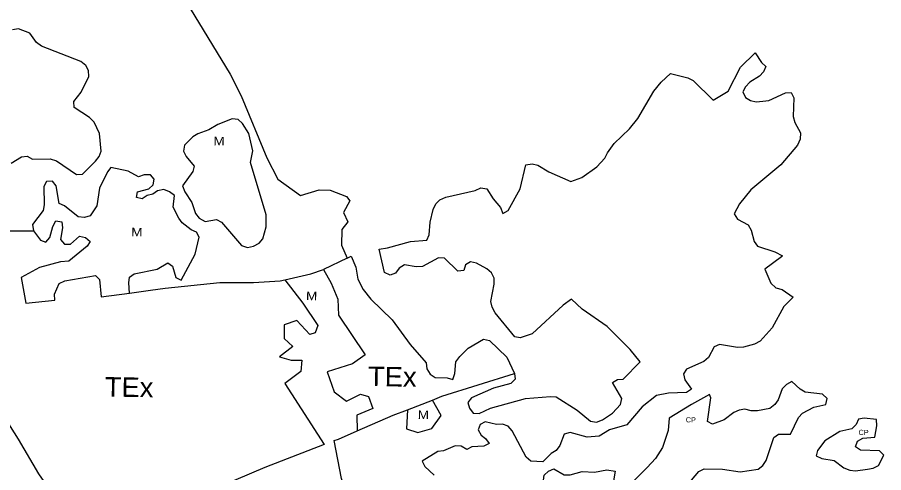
# Model space of a CAD drawing. Extents: x 713589 to 726391, y 7177764 to 7191819.
# Drawn here: x 719111 to 720179, y 7178472 to 7179033 of the extents above; entities that cross this region are included whole.
import ezdxf
from ezdxf.enums import TextEntityAlignment as Align

# ---------------------------------------------------------------- set-up
doc = ezdxf.new("R2010")
doc.units = 0
doc.header["$LTSCALE"] = 2.6
doc.layers.add('63', color=7, linetype='Continuous', lineweight=25)

msp = doc.modelspace()

# ---------------------------------------------------------------- linework, layer by layer
at = {"layer": '63'}
for p, q in [((719516.99, 7178736.28), (719487.86, 7178722.39)), ((719591.53, 7178549.49), (719622.15, 7178561.43))]:
    msp.add_line(p, q, dxfattribs=at)
for points in [[(718838.82, 7179163.06), (718828.12, 7179158.53), (718794.44, 7179144.27), (718739.17, 7179106.93), (718770.73, 7179057.83), (718801.73, 7179009.6), (718825.05, 7178971.22), (718875.74, 7178887.82), (718880.38, 7178880.19), (718880.89, 7178879.35), (718890.45, 7178864.16), (718971.65, 7178735.2), (719013.14, 7178669.3), (719106.43, 7178521.14), (719111.47, 7178513.14), (719136.8, 7178470.37), (719165.62, 7178428.86), (719189.56, 7178386.56), (719224.52, 7178313.68)], [(719323.63, 7179043.62), (719372.98, 7178962.99), (719386.46, 7178936), (719418.04, 7178859.65), (719431.53, 7178833.65), (719459.49, 7178813.24), (719482.53, 7178820.48), (719496.02, 7178819.82), (719516.42, 7178811.92), (719520.37, 7178806.98), (719512.47, 7178792.5), (719518.06, 7178780.99), (719510.49, 7178771.44), (719510.16, 7178752.03), (719516.99, 7178736.28)], [(719102.73, 7178852.99), (719115.57, 7178860.89), (719122.81, 7178861.87), (719129.06, 7178857.92), (719151.1, 7178858.58), (719158.67, 7178855.94), (719183.35, 7178839.16), (719190.92, 7178839.49), (719206.72, 7178855.61), (719211.33, 7178861.53), (719213.96, 7178868.11), (719211.66, 7178889.83), (719205.41, 7178903.65), (719199.49, 7178909.25), (719180.4, 7178921.75), (719180.08, 7178928.99), (719189.29, 7178940.51), (719198.51, 7178959.92), (719198.18, 7178967.16), (719194.89, 7178973.42), (719188.97, 7178978.35), (719140.27, 7178997.45), (719134.35, 7179001.73), (719125.79, 7179013.25), (719111.97, 7179018.51), (719104.73, 7179017.53)], [(719723.31, 7178594.23), (719724.3, 7178586.99), (719719.03, 7178581.73), (719697.64, 7178576.14), (719670.33, 7178563.97), (719666.05, 7178558.38), (719668.02, 7178551.46), (719672.3, 7178545.21), (719679.87, 7178544.88), (719693.69, 7178551.46), (719737.13, 7178563.3), (719767.73, 7178565.93), (719774.97, 7178565.27), (719800.64, 7178549.14), (719817.09, 7178535.31), (719824.33, 7178534.33), (719831.9, 7178536.96), (719844.4, 7178545.18), (719853.95, 7178556.04), (719855.59, 7178563.28), (719844.08, 7178583.02), (719850.33, 7178586.64), (719857.57, 7178586.97), (719878.15, 7178608.35), (719866.13, 7178623.5), (719837.51, 7178651.8), (719806.91, 7178673.53), (719793.82, 7178685.48), (719783.22, 7178678.14), (719745.04, 7178642.93), (719730.56, 7178638), (719723.65, 7178639.32), (719699.63, 7178668.94), (719696.01, 7178675.85), (719694.04, 7178682.76), (719698.32, 7178704.15), (719698.32, 7178711.72), (719695.03, 7178718.3), (719689.44, 7178722.91), (719676.61, 7178730.15), (719669.37, 7178731.47), (719663.12, 7178727.85), (719660.81, 7178720.94), (719653.57, 7178719.95), (719637.12, 7178736.08), (719629.55, 7178736.41), (719609.81, 7178725.88), (719602.24, 7178725.55), (719587.76, 7178727.86), (719581.18, 7178723.91), (719576.57, 7178717.66), (719569.99, 7178715.03), (719563.08, 7178718.32), (719556.52, 7178747.34), (719567.03, 7178748.92), (719595.33, 7178756.49), (719615.42, 7178758.3), (719618.04, 7178765.04), (719619.36, 7178780.51), (719623.31, 7178796.3), (719626.6, 7178803.21), (719631.54, 7178808.15), (719638.78, 7178811.11), (719674.98, 7178819.66), (719681.89, 7178822.95), (719689.13, 7178821.63), (719697.02, 7178809.12), (719706.24, 7178798.59), (719709.2, 7178791.35), (719715.45, 7178794.97), (719730.59, 7178821.62), (719737.51, 7178851.24), (719745.08, 7178852.55), (719752.32, 7178850.58), (719765.81, 7178842.35), (719792.79, 7178830.49), (719806.28, 7178835.43), (719824.71, 7178848.59), (719834.91, 7178859.45), (719837.88, 7178866.03), (719846.43, 7178877.21), (719865.19, 7178895.64), (719875.4, 7178908.14), (719895.15, 7178941.7), (719904.04, 7178952.89), (719915.55, 7178963.42), (719937.27, 7178958.48), (719943.52, 7178955.19), (719968.23, 7178930.88), (719986.63, 7178942.02), (720002.1, 7178971.3), (720020.2, 7178989.12), (720028.1, 7178977.22), (720033.36, 7178972.28)], [(720033.36, 7178972.28), (720030.4, 7178965.7), (720025.46, 7178960.44), (720013.62, 7178952.87), (720008.35, 7178947.28), (720004.73, 7178941.03), (720008.02, 7178934.11), (720014.27, 7178930.16), (720021.18, 7178928.85), (720029.41, 7178929.5), (720036.98, 7178930.49), (720057.38, 7178939.7), (720064.62, 7178940.36), (720067.58, 7178933.45), (720066.92, 7178910.74), (720068.89, 7178903.17), (720075.8, 7178890.66), (720075.47, 7178882.77), (720072.18, 7178875.53), (720051.77, 7178851.18), (720014.91, 7178820.25), (720000.76, 7178803.15), (719994.17, 7178790.64), (719998.45, 7178784.39), (720011.61, 7178777.15), (720015.23, 7178770.56), (720018.85, 7178756.74), (720023.12, 7178750.82), (720044.18, 7178743.9), (720053.8, 7178738.87), (720052.41, 7178737.65), (720032.03, 7178722.65), (720039.57, 7178705.4), (720045.49, 7178699.81), (720053.39, 7178697.5), (720066.88, 7178687.96), (720055.36, 7178676.77), (720041.2, 7178650.45), (720026.06, 7178634), (720019.48, 7178630.05), (720005.66, 7178626.43), (719998.42, 7178626.11), (719976.04, 7178629.73), (719969.46, 7178627.1), (719962.55, 7178613.94), (719956.96, 7178609), (719935.56, 7178599.46), (719931.61, 7178593.54), (719933.26, 7178586.3), (719941.81, 7178574.78), (719935.56, 7178570.83), (719913.18, 7178569.85), (719898.37, 7178566.89), (719880.93, 7178553.07), (719861.84, 7178531.03), (719840.45, 7178524.78), (719827.61, 7178516.88), (719813.13, 7178515.9), (719792.08, 7178521.5), (719784.51, 7178519.2), (719779.24, 7178505.38), (719774.96, 7178499.45), (719768.71, 7178495.5), (719758.5, 7178485.31), (719743.7, 7178486.3), (719737.77, 7178490.9), (719720.34, 7178523.48), (719715.4, 7178529.08), (719708.82, 7178531.71), (719701.25, 7178531.39), (719687.43, 7178534.68), (719681.18, 7178531.39), (719678.55, 7178524.81), (719682.17, 7178518.23), (719687.76, 7178513.95), (719692.04, 7178508.02), (719685.45, 7178504.73), (719670.97, 7178503.75), (719664.72, 7178500.46), (719657.48, 7178504.41), (719650.24, 7178505.07), (719636.09, 7178498.82), (719628.85, 7178498.16), (719609.76, 7178486.32), (719612.72, 7178479.77), (719624.24, 7178468.88)], [(719248.81, 7178693.26), (719247.82, 7178705.87), (719248.81, 7178712.78), (719254.41, 7178717.06), (719283.04, 7178722.65), (719295.87, 7178730.22), (719301.8, 7178726.27), (719306.07, 7178712.44), (719312.32, 7178709.15), (719329.77, 7178741.07), (719334.71, 7178762.13), (719331.42, 7178768.38), (719324.84, 7178771.02), (719313.65, 7178779.57), (719309.7, 7178785.5), (719302.8, 7178798.99), (719304.44, 7178813.47), (719298.19, 7178817.75), (719290.95, 7178820.71), (719283.38, 7178819.07), (719277.46, 7178814.79), (719270.55, 7178813.15), (719264.3, 7178809.2), (719257.39, 7178810.84), (719258.7, 7178817.75), (719272.53, 7178821.7), (719277.79, 7178826.64), (719279.11, 7178833.55), (719274.5, 7178838.81), (719266.93, 7178838.81), (719260.02, 7178836.51), (719247.19, 7178843.42), (719225.8, 7178848.04), (719221.52, 7178842.44), (719211.65, 7178822.37), (719208.35, 7178800.65), (719200.45, 7178788.48), (719193.21, 7178786.18), (719185.64, 7178787.16), (719168.86, 7178800.66), (719162.28, 7178803.62), (719158.34, 7178825.34), (719153.73, 7178830.94), (719146.49, 7178830.61), (719143.2, 7178824.36), (719143.53, 7178801.98), (719142.21, 7178795.07), (719129.04, 7178777.63), (719130.54, 7178769.74)], [(719030.63, 7178805), (719050.19, 7178772.78), (719092.19, 7178769.74), (719130.54, 7178769.74)], [(719130.54, 7178769.74), (719139.24, 7178758.54), (719145.82, 7178755.91), (719150.76, 7178761.5), (719154.38, 7178775.32), (719158, 7178782.23), (719165.24, 7178780.92), (719166.23, 7178773.68), (719163.92, 7178759.2), (719168.53, 7178753.6), (719176.1, 7178753.27), (719187.29, 7178763.14), (719194.52, 7178761.49), (719200.45, 7178756.89), (719196.5, 7178750.96), (719173.93, 7178732.62), (719173.91, 7178732.61), (719163.71, 7178731.62), (719137.71, 7178724.72), (719115.33, 7178712.21), (719121.06, 7178680.78), (719156.78, 7178684.58), (719156.34, 7178691.74), (719162.27, 7178704.9), (719169.18, 7178708.19), (719206.69, 7178714.76), (719211.96, 7178709.83), (719214.02, 7178688.7), (719214.03, 7178688.7), (719248.81, 7178693.26)], [(719516.99, 7178736.28), (719521.88, 7178738.61), (719527.87, 7178724.91), (719530.17, 7178710.43), (719536.75, 7178697.6), (719546.29, 7178685.75), (719572.61, 7178660.07), (719594.98, 7178629.8), (719614.39, 7178607.09), (719615.38, 7178599.85), (719619.33, 7178593.27), (719625.58, 7178588.99), (719640.39, 7178588.65), (719647.3, 7178586.68), (719649.93, 7178593.92), (719651.25, 7178608.4), (719655.86, 7178614.98), (719666.39, 7178625.18), (719685.15, 7178636.36), (719692.72, 7178634.72), (719714.1, 7178614.31), (719723.31, 7178594.23)], [(719440.31, 7178709.52), (719472.38, 7178716.76), (719487.86, 7178722.39)], [(719487.86, 7178722.39), (719497.38, 7178705.57), (719505.61, 7178685.82), (719506.59, 7178666.08), (719539.49, 7178617.04), (719523.69, 7178606.18), (719492.46, 7178596.21), (719501.19, 7178571.57), (719516.32, 7178560.05), (719533.76, 7178568.6), (719543.31, 7178565.64), (719548.9, 7178551.16), (719529.15, 7178542.6), (719529.42, 7178523.4)], [(719248.81, 7178693.26), (719274.88, 7178696.68), (719292.7, 7178699.02), (719359.96, 7178706.16), (719401.62, 7178706.24), (719434.53, 7178708.21), (719440.31, 7178709.52)], [(719440.31, 7178709.52), (719462.37, 7178680.83), (719480.8, 7178653.18), (719477.83, 7178644.3), (719470.92, 7178641.99), (719455.13, 7178659.44), (719439.66, 7178653.85), (719439.33, 7178637.39), (719450.19, 7178627.52), (719433.73, 7178614.69), (719448.21, 7178610.74), (719461.05, 7178610.73), (719460.06, 7178596.58), (719440.08, 7178581.73), (719488.64, 7178506.58), (719415.46, 7178478.26), (719343.97, 7178447.76), (719330.5, 7178442.01), (719305.1, 7178432.59)], [(719622.15, 7178561.43), (719633.92, 7178566.02), (719723.33, 7178594.07), (719723.31, 7178594.23)], [(719941.59, 7178462.63), (719950.8, 7178473.49), (719957.06, 7178476.78), (719979.76, 7178476.12), (720001.81, 7178473.15), (720023.86, 7178476.11), (720029.45, 7178480.72), (720033.73, 7178486.97), (720042.95, 7178515.27), (720048.87, 7178519.22), (720063.68, 7178519.21), (720073.56, 7178539.94), (720078.5, 7178545.21), (720092.32, 7178552.77), (720107.13, 7178556.06), (720108.77, 7178563.3), (720103.18, 7178568.57), (720081.79, 7178571.2), (720075.54, 7178574.82), (720065.34, 7178584.37), (720058.76, 7178580.75), (720053.49, 7178575.16), (720048.55, 7178561.67), (720044.27, 7178555.74), (720038.02, 7178551.14), (720022.88, 7178548.18), (720014.98, 7178548.18), (720007.42, 7178550.16), (720000.51, 7178548.84), (719993.92, 7178545.88), (719981.75, 7178537), (719967.6, 7178531.73), (719961.34, 7178535.03), (719965.3, 7178563.98), (719963.91, 7178568.07), (719941.52, 7178556.06), (719913.9, 7178538.98), (719912.97, 7178523.85), (719905.73, 7178502.79), (719897.17, 7178489.3), (719887.05, 7178478.53), (719870.84, 7178462.32)], [(719591.53, 7178549.49), (719590.36, 7178526.14), (719604.18, 7178521.53), (719621.62, 7178526.46), (719633.14, 7178542.26), (719622.15, 7178561.43)], [(719529.42, 7178523.4), (719574.03, 7178542.66), (719591.53, 7178549.49)], [(719305.1, 7178432.59), (719300.09, 7178395.22), (719300.42, 7178370.54), (719302.06, 7178360.34), (719291.53, 7178352.77), (719295.15, 7178345.53), (719309.63, 7178344.87), (719315.88, 7178336.31), (719398.8, 7178345.84), (719440.6, 7178361.3), (719458.7, 7178372.82), (719483.05, 7178381.7), (719475.49, 7178407.69), (719507.76, 7178413.92), (719513.53, 7178416.75), (719523.87, 7178421.84), (719510.05, 7178464.62), (719501.14, 7178511.41), (719506.24, 7178513.39), (719529.42, 7178523.4)], [(719735.45, 7178401.4), (719739.4, 7178407.98), (719745, 7178421.8), (719747.96, 7178436.28), (719751.59, 7178442.53), (719757.18, 7178447.46), (719760.15, 7178468.85), (719765.41, 7178473.79), (719771.99, 7178476.75), (719784.83, 7178469.18), (719792.07, 7178469.5), (719806.87, 7178473.45), (719822.01, 7178472.79), (719837.15, 7178475.42), (719847.65, 7178473.86), (719837.95, 7178417.68)]]:
    msp.add_lwpolyline(points, dxfattribs=at)
for points in [[(719356.1, 7178783.84), (719362.35, 7178780.55), (719386.7, 7178751.59), (719394.27, 7178749.28), (719401.84, 7178750.93), (719408.75, 7178754.55), (719413.36, 7178760.14), (719417.31, 7178774.62), (719417.31, 7178789.43), (719397.91, 7178853.93), (719400.87, 7178868.41), (719395.94, 7178889.8), (719388.04, 7178901.97), (719382.78, 7178906.91), (719375.21, 7178907.9), (719357.64, 7178900.67), (719346.58, 7178894.41), (719333.09, 7178889.48), (719326.83, 7178885.53), (719316.63, 7178875.33), (719315.31, 7178867.76), (719318.6, 7178861.18), (719328.47, 7178849.66), (719326.83, 7178842.75), (719314.32, 7178825.31), (719316.95, 7178817.74), (719325.5, 7178804.91), (719330.11, 7178791.09), (719334.71, 7178785.49), (719341.95, 7178781.21)], [(720154.51, 7178539.27), (720147.6, 7178537.95), (720144.64, 7178531.37), (720139.37, 7178526.11), (720124.56, 7178522.49), (720105.8, 7178510.98), (720096.92, 7178499.46), (720095.27, 7178492.55), (720102.18, 7178489.26), (720117.32, 7178486.95), (720129.49, 7178478.07), (720136.73, 7178475.1), (720143.97, 7178474.12), (720158.45, 7178476.09), (720165.69, 7178477.4), (720171.94, 7178480.69), (720178.52, 7178493.52), (720173.26, 7178498.79), (720149.9, 7178499.78), (720143.97, 7178503.73), (720146.28, 7178510.97), (720152.86, 7178514.59), (720167.67, 7178515.57), (720169.97, 7178529.72), (720169.65, 7178537.62)]]:
    msp.add_lwpolyline(points, close=True, dxfattribs=at)

# ---------------------------------------------------------------- texts
for s, height, width, p in [('M', 10.4, 1.2, (719359.16, 7178875.23)), ('M', 10.4, 1.2, (719257.85, 7178763.11)), ('M', 10.4, 1.2, (719473.26, 7178684.41)), ('TEx', 24, 1.05, (719572.6, 7178578.22)), ('TEx', 24, 1.05, (719248.13, 7178565.29)), ('M', 10.4, 1.2, (719611.04, 7178538.08)), ('CP', 6.4, 1.05, (719940.74, 7178533.84)), ('CP', 6.4, 1.05, (720153.68, 7178518.34))]:
    msp.add_text(s, height=height, rotation=359.062, dxfattribs=dict(at, width=width)).set_placement(p, align=Align.CENTER)

doc.saveas('drawing.dxf')
